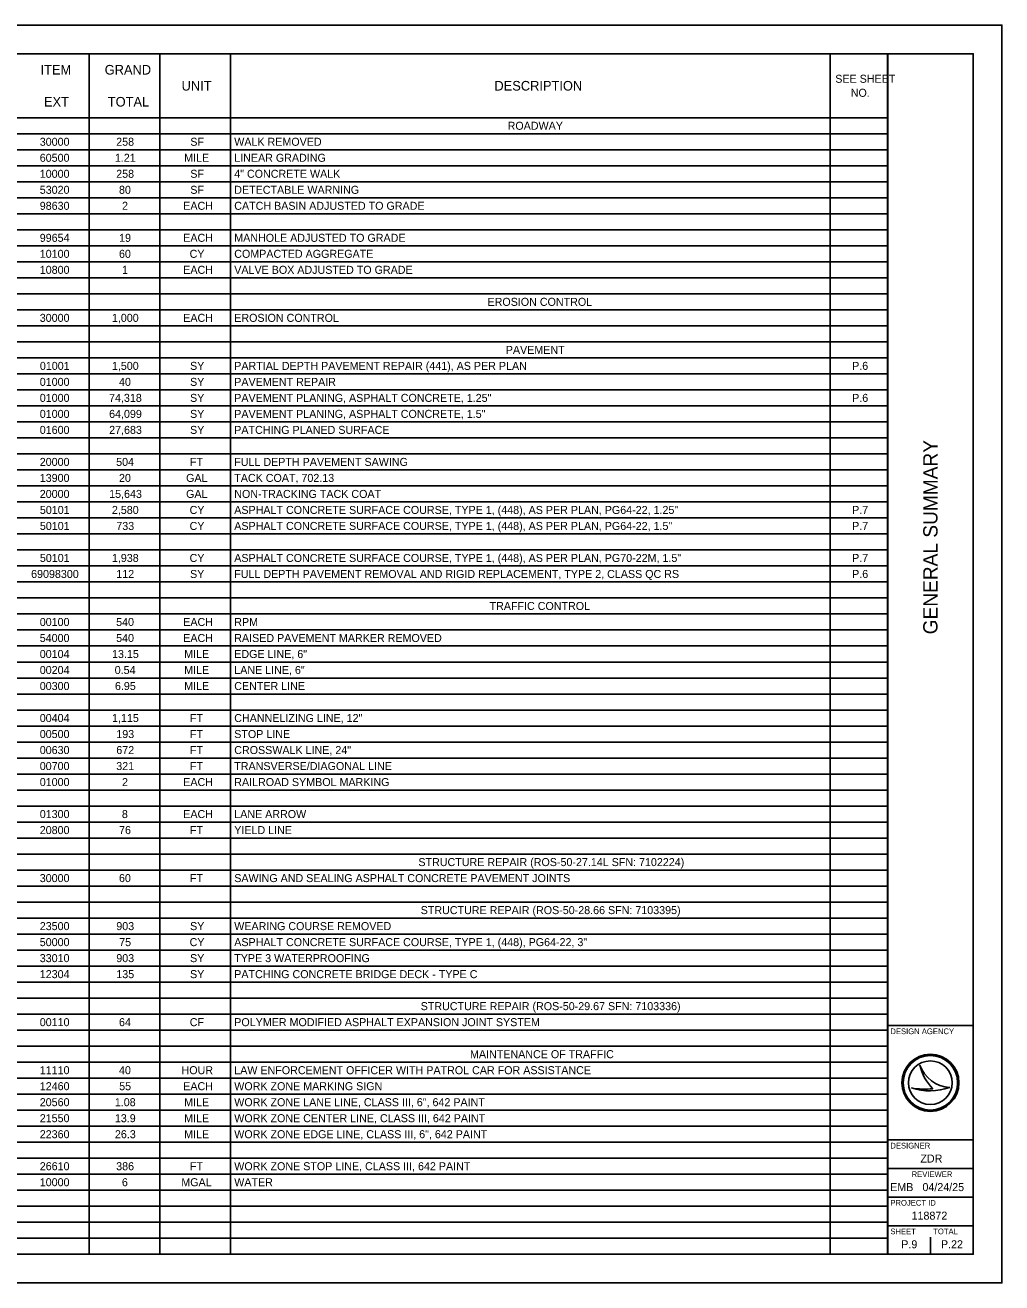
# Model space of a CAD drawing. Extents: x 0 to 34, y 0 to 22.
# Drawn here: x 16.92 to 34, y 0 to 22 of the extents above; entities that cross this region are included whole.
import ezdxf

# ---------------------------------------------------------------- set-up
doc = ezdxf.new("R2010")
doc.units = 0
for name, color, linetype in [('SH_Border', 7, 'Continuous'), ('SH_Cut_Line', 7, 'Continuous'), ('SH_Data', 7, 'Continuous'), ('SH_Text', 7, 'Continuous')]:
    doc.layers.add(name, color=color, linetype=linetype)

msp = doc.modelspace()

# ---------------------------------------------------------------- linework, layer by layer
at = {"layer": 'SH_Border'}
for p, q in [((32, 0.5), (32, 21.5)), ((32, 4.5), (33.5, 4.5)), ((32, 2.5), (33.5, 2.5)), ((32, 2), (33.5, 2)), ((32, 1.5), (33.5, 1.5)), ((32, 1), (33.5, 1))]:
    msp.add_line(p, q, dxfattribs=at)
msp.add_lwpolyline([(1.5, 21.5), (33.5, 21.5), (33.5, 0.5), (1.5, 0.5)], close=True, dxfattribs=at)
at = {"layer": 'SH_Cut_Line'}
msp.add_lwpolyline([(0, 0), (34, 0), (34, 22), (0, 22)], close=True, dxfattribs=at)
at = {"layer": 'SH_Data'}
for p, q in [((32.567, 3.81), (32.567, 3.81)), ((32.417, 3.41), (32.417, 3.41)), ((32.75, 3.5), (32.75, 3.5)), ((33.087, 3.419), (33.087, 3.419)), ((32.375, 0.675), (32.375, 0.675)), ((32.75, 0.5), (32.75, 0.8))]:
    msp.add_line(p, q, dxfattribs=at)
for radius in [0.5, 0.477, 0.477, 0.382]:
    msp.add_circle((32.75, 3.5), radius, dxfattribs=at)
for centre, radius, start, end in [((33.116, 3.998), 0.58, 198.9257, 198.9319), ((33.347, 3.97), 0.796, 191.6379, 191.6421), ((33.116, 3.998), 0.58, 198.9319, 267.1657), ((33.347, 3.97), 0.796, 191.6421, 226.0947), ((32.739, 4.37), 1.013, 251.4576, 290.0832), ((32.648, 4.654), 1.266, 259.4964, 259.4995), ((32.739, 4.37), 1.013, 251.4527, 251.4576), ((32.648, 4.654), 1.266, 259.4995, 276.6672)]:
    msp.add_arc(centre, radius, start, end, dxfattribs=at)
at = {"layer": 'SH_Text'}
for p, q in [((1.5, 21.5), (32.004, 21.5)), ((18.036, 21.5), (18.036, 0.5)), ((19.272, 21.5), (19.272, 0.5)), ((20.507, 21.5), (20.507, 0.5)), ((30.999, 21.5), (30.999, 0.5)), ((32.004, 21.5), (32.004, 0.5)), ((1.5, 20.38), (32.004, 20.38)), ((1.5, 20.1), (32.004, 20.1)), ((1.5, 19.82), (32.004, 19.82)), ((1.5, 19.54), (32.004, 19.54)), ((1.5, 19.26), (32.004, 19.26)), ((1.5, 18.98), (32.004, 18.98)), ((1.5, 18.7), (32.004, 18.7)), ((1.5, 18.42), (32.004, 18.42)), ((1.5, 18.14), (32.004, 18.14)), ((1.5, 17.86), (32.004, 17.86)), ((1.5, 17.58), (32.004, 17.58)), ((1.5, 17.3), (32.004, 17.3)), ((1.5, 17.02), (32.004, 17.02)), ((1.5, 16.74), (32.004, 16.74)), ((1.5, 16.46), (32.004, 16.46)), ((1.5, 16.18), (32.004, 16.18)), ((1.5, 15.9), (32.004, 15.9)), ((1.5, 15.62), (32.004, 15.62)), ((1.5, 15.34), (32.004, 15.34)), ((1.5, 15.06), (32.004, 15.06)), ((1.5, 14.78), (32.004, 14.78)), ((1.5, 14.5), (32.004, 14.5)), ((1.5, 14.22), (32.004, 14.22)), ((1.5, 13.94), (32.004, 13.94)), ((1.5, 13.66), (32.004, 13.66)), ((1.5, 13.38), (32.004, 13.38)), ((1.5, 13.1), (32.004, 13.1)), ((1.5, 12.82), (32.004, 12.82)), ((1.5, 12.54), (32.004, 12.54)), ((1.5, 12.26), (32.004, 12.26)), ((1.5, 11.98), (32.004, 11.98)), ((1.5, 11.7), (32.004, 11.7)), ((1.5, 11.42), (32.004, 11.42)), ((1.5, 11.14), (32.004, 11.14)), ((1.5, 10.86), (32.004, 10.86)), ((1.5, 10.58), (32.004, 10.58)), ((1.5, 10.3), (32.004, 10.3)), ((1.5, 10.02), (32.004, 10.02)), ((1.5, 9.74), (32.004, 9.74)), ((1.5, 9.46), (32.004, 9.46)), ((1.5, 9.18), (32.004, 9.18)), ((1.5, 8.9), (32.004, 8.9)), ((1.5, 8.62), (32.004, 8.62)), ((1.5, 8.34), (32.004, 8.34)), ((1.5, 8.06), (32.004, 8.06)), ((1.5, 7.78), (32.004, 7.78)), ((1.5, 7.5), (32.004, 7.5)), ((1.5, 7.22), (32.004, 7.22)), ((1.5, 6.94), (32.004, 6.94)), ((1.5, 6.66), (32.004, 6.66)), ((1.5, 6.38), (32.004, 6.38)), ((1.5, 6.1), (32.004, 6.1)), ((1.5, 5.82), (32.004, 5.82)), ((1.5, 5.54), (32.004, 5.54)), ((1.5, 5.26), (32.004, 5.26)), ((1.5, 4.98), (32.004, 4.98)), ((1.5, 4.7), (32.004, 4.7)), ((1.5, 4.42), (32.004, 4.42)), ((1.5, 4.14), (32.004, 4.14)), ((1.5, 3.86), (32.004, 3.86)), ((1.5, 3.58), (32.004, 3.58)), ((1.5, 3.3), (32.004, 3.3)), ((1.5, 3.02), (32.004, 3.02)), ((1.5, 2.74), (32.004, 2.74)), ((1.5, 2.46), (32.004, 2.46)), ((1.5, 2.18), (32.004, 2.18)), ((1.5, 1.9), (32.004, 1.9)), ((1.5, 1.62), (32.004, 1.62)), ((1.5, 1.34), (32.004, 1.34)), ((1.5, 1.06), (32.004, 1.06)), ((1.5, 0.78), (32.004, 0.78)), ((1.5, 0.5), (32.004, 0.5))]:
    msp.add_line(p, q, dxfattribs=at)

# ---------------------------------------------------------------- texts
at = {"layer": 'SH_Data'}
msp.add_text('GENERAL SUMMARY', height=0.25, rotation=90, dxfattribs=at).set_placement((32.875, 11.344))
for s, height, p in [('DESIGN AGENCY', 0.1, (32.05, 4.35)), ('DESIGNER', 0.1, (32.05, 2.35)), ('ZDR', 0.14, (32.575, 2.105)), ('REVIEWER', 0.1, (32.422, 1.85)), ('EMB', 0.14, (32.047, 1.605)), ('04/24/25', 0.14, (32.611, 1.605)), ('PROJECT ID', 0.1, (32.05, 1.35)), ('118872', 0.14, (32.421, 1.105)), ('SHEET', 0.1, (32.05, 0.85)), ('TOTAL', 0.1, (32.8, 0.85)), ('P.9', 0.14, (32.24, 0.605)), ('P.22', 0.14, (32.935, 0.605))]:
    msp.add_text(s, height=height, dxfattribs=at).set_placement(p)
at = {"layer": 'SH_Text'}
for s, height, p in [('ITEM', 0.168, (17.184, 21.136)), ('GRAND', 0.168, (18.307, 21.136)), ('SEE SHEET ', 0.14, (31.086, 20.992)), ('UNIT', 0.168, (19.652, 20.856)), ('DESCRIPTION', 0.168, (25.124, 20.856)), ('EXT', 0.168, (17.244, 20.576)), ('TOTAL', 0.168, (18.361, 20.576)), ('NO.', 0.14, (31.357, 20.747)), ('ROADWAY', 0.14, (25.355, 20.17)), ('30000', 0.14, (17.171, 19.89)), ('258', 0.14, (18.508, 19.89)), ('SF', 0.14, (19.804, 19.89)), ('WALK REMOVED', 0.14, (20.573, 19.89)), ('60500', 0.14, (17.171, 19.61)), ('1.21', 0.14, (18.485, 19.61)), ('MILE', 0.14, (19.697, 19.61)), ('LINEAR GRADING', 0.14, (20.573, 19.61)), ('10000', 0.14, (17.171, 19.33)), ('258', 0.14, (18.508, 19.33)), ('SF', 0.14, (19.804, 19.33)), ('4" CONCRETE WALK', 0.14, (20.573, 19.33)), ('53020', 0.14, (17.171, 19.05)), ('80', 0.14, (18.557, 19.05)), ('SF', 0.14, (19.804, 19.05)), ('DETECTABLE WARNING', 0.14, (20.573, 19.05)), ('98630', 0.14, (17.171, 18.77)), ('2', 0.14, (18.61, 18.77)), ('EACH', 0.14, (19.681, 18.77)), ('CATCH BASIN ADJUSTED TO GRADE', 0.14, (20.573, 18.77)), ('99654', 0.14, (17.171, 18.21)), ('19', 0.14, (18.559, 18.21)), ('EACH', 0.14, (19.681, 18.21)), ('MANHOLE ADJUSTED TO GRADE', 0.14, (20.573, 18.21)), ('10100', 0.14, (17.171, 17.93)), ('60', 0.14, (18.557, 17.93)), ('CY', 0.14, (19.792, 17.93)), ('COMPACTED AGGREGATE', 0.14, (20.573, 17.93)), ('10800', 0.14, (17.171, 17.65)), ('1', 0.14, (18.61, 17.65)), ('EACH', 0.14, (19.681, 17.65)), ('VALVE BOX ADJUSTED TO GRADE', 0.14, (20.573, 17.65)), ('EROSION CONTROL', 0.14, (25.003, 17.09)), ('30000', 0.14, (17.171, 16.81)), ('1,000', 0.14, (18.433, 16.81)), ('EACH', 0.14, (19.681, 16.81)), ('EROSION CONTROL', 0.14, (20.573, 16.81)), ('PAVEMENT', 0.14, (25.323, 16.25)), ('01001', 0.14, (17.173, 15.97)), ('1,500', 0.14, (18.433, 15.97)), ('SY', 0.14, (19.8, 15.97)), ('PARTIAL DEPTH PAVEMENT REPAIR (441), AS PER PLAN', 0.14, (20.573, 15.97)), ('P.6', 0.14, (31.381, 15.97)), ('01000', 0.14, (17.171, 15.69)), ('40', 0.14, (18.557, 15.69)), ('SY', 0.14, (19.8, 15.69)), ('PAVEMENT REPAIR', 0.14, (20.573, 15.69)), ('01000', 0.14, (17.171, 15.41)), ('74,318', 0.14, (18.383, 15.41)), ('SY', 0.14, (19.8, 15.41)), ('PAVEMENT PLANING, ASPHALT CONCRETE, 1.25"', 0.14, (20.573, 15.41)), ('P.6', 0.14, (31.381, 15.41)), ('01000', 0.14, (17.171, 15.13)), ('64,099', 0.14, (18.384, 15.13)), ('SY', 0.14, (19.8, 15.13)), ('PAVEMENT PLANING, ASPHALT CONCRETE, 1.5"', 0.14, (20.573, 15.13)), ('01600', 0.14, (17.171, 14.85)), ('27,683', 0.14, (18.385, 14.85)), ('SY', 0.14, (19.8, 14.85)), ('PATCHING PLANED SURFACE', 0.14, (20.573, 14.85)), ('20000', 0.14, (17.171, 14.29)), ('504', 0.14, (18.507, 14.29)), ('FT', 0.14, (19.797, 14.29)), ('FULL DEPTH PAVEMENT SAWING', 0.14, (20.573, 14.29)), ('13900', 0.14, (17.171, 14.01)), ('20', 0.14, (18.557, 14.01)), ('GAL', 0.14, (19.731, 14.01)), ('TACK COAT, 702.13', 0.14, (20.573, 14.01)), ('20000', 0.14, (17.171, 13.73)), ('15,643', 0.14, (18.385, 13.73)), ('GAL', 0.14, (19.731, 13.73)), ('NON-TRACKING TACK COAT', 0.14, (20.573, 13.73)), ('50101', 0.14, (17.173, 13.45)), ('2,580', 0.14, (18.433, 13.45)), ('CY', 0.14, (19.792, 13.45)), ('ASPHALT CONCRETE SURFACE COURSE, TYPE 1, (448), AS PER PLAN, PG64-22, 1.25"', 0.14, (20.573, 13.45)), ('P.7', 0.14, (31.381, 13.45)), ('50101', 0.14, (17.173, 13.17)), ('733', 0.14, (18.51, 13.17)), ('CY', 0.14, (19.792, 13.17)), ('ASPHALT CONCRETE SURFACE COURSE, TYPE 1, (448), AS PER PLAN, PG64-22, 1.5"', 0.14, (20.573, 13.17)), ('P.7', 0.14, (31.381, 13.17)), ('50101', 0.14, (17.173, 12.61)), ('1,938', 0.14, (18.433, 12.61)), ('CY', 0.14, (19.792, 12.61)), ('ASPHALT CONCRETE SURFACE COURSE, TYPE 1, (448), AS PER PLAN, PG70-22M, 1.5"', 0.14, (20.573, 12.61)), ('P.7', 0.14, (31.381, 12.61)), ('69098300', 0.14, (17.02, 12.33)), ('112', 0.14, (18.51, 12.33)), ('SY', 0.14, (19.8, 12.33)), ('FULL DEPTH PAVEMENT REMOVAL AND RIGID REPLACEMENT, TYPE 2, CLASS QC RS', 0.14, (20.573, 12.33)), ('P.6', 0.14, (31.381, 12.33)), ('TRAFFIC CONTROL', 0.14, (25.039, 11.77)), ('00100', 0.14, (17.171, 11.49)), ('540', 0.14, (18.507, 11.49)), ('EACH', 0.14, (19.681, 11.49)), ('RPM', 0.14, (20.573, 11.49)), ('54000', 0.14, (17.171, 11.21)), ('540', 0.14, (18.507, 11.21)), ('EACH', 0.14, (19.681, 11.21)), ('RAISED PAVEMENT MARKER REMOVED', 0.14, (20.573, 11.21)), ('00104', 0.14, (17.171, 10.93)), ('13.15', 0.14, (18.435, 10.93)), ('MILE', 0.14, (19.697, 10.93)), ('EDGE LINE, 6"', 0.14, (20.573, 10.93)), ('00204', 0.14, (17.171, 10.65)), ('0.54', 0.14, (18.482, 10.65)), ('MILE', 0.14, (19.697, 10.65)), ('LANE LINE, 6"', 0.14, (20.573, 10.65)), ('00300', 0.14, (17.171, 10.37)), ('6.95', 0.14, (18.486, 10.37)), ('MILE', 0.14, (19.697, 10.37)), ('CENTER LINE', 0.14, (20.573, 10.37)), ('00404', 0.14, (17.171, 9.81)), ('1,115', 0.14, (18.435, 9.81)), ('FT', 0.14, (19.797, 9.81)), ('CHANNELIZING LINE, 12"', 0.14, (20.573, 9.81)), ('00500', 0.14, (17.171, 9.53)), ('193', 0.14, (18.51, 9.53)), ('FT', 0.14, (19.797, 9.53)), ('STOP LINE', 0.14, (20.573, 9.53)), ('00630', 0.14, (17.171, 9.25)), ('672', 0.14, (18.51, 9.25)), ('FT', 0.14, (19.797, 9.25)), ('CROSSWALK LINE, 24"', 0.14, (20.573, 9.25)), ('00700', 0.14, (17.171, 8.97)), ('321', 0.14, (18.509, 8.97)), ('FT', 0.14, (19.797, 8.97)), ('TRANSVERSE/DIAGONAL LINE', 0.14, (20.573, 8.97)), ('01000', 0.14, (17.171, 8.69)), ('2', 0.14, (18.61, 8.69)), ('EACH', 0.14, (19.681, 8.69)), ('RAILROAD SYMBOL MARKING', 0.14, (20.573, 8.69)), ('01300', 0.14, (17.171, 8.13)), ('8', 0.14, (18.608, 8.13)), ('EACH', 0.14, (19.681, 8.13)), ('LANE ARROW', 0.14, (20.573, 8.13)), ('20800', 0.14, (17.171, 7.85)), ('76', 0.14, (18.558, 7.85)), ('FT', 0.14, (19.797, 7.85)), ('YIELD LINE', 0.14, (20.573, 7.85)), ('STRUCTURE REPAIR (ROS-50-27.14L SFN: 7102224)', 0.14, (23.794, 7.29)), ('30000', 0.14, (17.171, 7.01)), ('60', 0.14, (18.557, 7.01)), ('FT', 0.14, (19.797, 7.01)), ('SAWING AND SEALING ASPHALT CONCRETE PAVEMENT JOINTS', 0.14, (20.573, 7.01)), ('STRUCTURE REPAIR (ROS-50-28.66 SFN: 7103395)', 0.14, (23.834, 6.45)), ('23500', 0.14, (17.171, 6.17)), ('903', 0.14, (18.51, 6.17)), ('SY', 0.14, (19.8, 6.17)), ('WEARING COURSE REMOVED', 0.14, (20.573, 6.17)), ('50000', 0.14, (17.171, 5.89)), ('75', 0.14, (18.56, 5.89)), ('CY', 0.14, (19.792, 5.89)), ('ASPHALT CONCRETE SURFACE COURSE, TYPE 1, (448), PG64-22, 3"', 0.14, (20.573, 5.89)), ('33010', 0.14, (17.171, 5.61)), ('903', 0.14, (18.51, 5.61)), ('SY', 0.14, (19.8, 5.61)), ('TYPE 3 WATERPROOFING', 0.14, (20.573, 5.61)), ('12304', 0.14, (17.171, 5.33)), ('135', 0.14, (18.51, 5.33)), ('SY', 0.14, (19.8, 5.33)), ('PATCHING CONCRETE BRIDGE DECK - TYPE C', 0.14, (20.573, 5.33)), ('STRUCTURE REPAIR (ROS-50-29.67 SFN: 7103336)', 0.14, (23.834, 4.77)), ('00110', 0.14, (17.171, 4.49)), ('64', 0.14, (18.557, 4.49)), ('CF', 0.14, (19.795, 4.49)), ('POLYMER MODIFIED ASPHALT EXPANSION JOINT SYSTEM', 0.14, (20.573, 4.49)), ('MAINTENANCE OF TRAFFIC', 0.14, (24.697, 3.93)), ('11110', 0.14, (17.171, 3.65)), ('40', 0.14, (18.557, 3.65)), ('HOUR', 0.14, (19.651, 3.65)), ('LAW ENFORCEMENT OFFICER WITH PATROL CAR FOR ASSISTANCE', 0.14, (20.573, 3.65)), ('12460', 0.14, (17.171, 3.37)), ('55', 0.14, (18.56, 3.37)), ('EACH', 0.14, (19.681, 3.37)), ('WORK ZONE MARKING SIGN', 0.14, (20.573, 3.37)), ('20560', 0.14, (17.171, 3.09)), ('1.08', 0.14, (18.484, 3.09)), ('MILE', 0.14, (19.697, 3.09)), ('WORK ZONE LANE LINE, CLASS III, 6", 642 PAINT', 0.14, (20.573, 3.09)), ('21550', 0.14, (17.171, 2.81)), ('13.9', 0.14, (18.485, 2.81)), ('MILE', 0.14, (19.697, 2.81)), ('WORK ZONE CENTER LINE, CLASS III, 642 PAINT', 0.14, (20.573, 2.81)), ('22360', 0.14, (17.171, 2.53)), ('26.3', 0.14, (18.486, 2.53)), ('MILE', 0.14, (19.697, 2.53)), ('WORK ZONE EDGE LINE, CLASS III, 6", 642 PAINT', 0.14, (20.573, 2.53)), ('26610', 0.14, (17.171, 1.97)), ('386', 0.14, (18.508, 1.97)), ('FT', 0.14, (19.797, 1.97)), ('WORK ZONE STOP LINE, CLASS III, 642 PAINT', 0.14, (20.573, 1.97)), ('10000', 0.14, (17.171, 1.69)), ('6', 0.14, (18.608, 1.69)), ('MGAL', 0.14, (19.647, 1.69)), ('WATER', 0.14, (20.573, 1.69))]:
    msp.add_text(s, height=height, dxfattribs=at).set_placement(p)

doc.saveas('drawing.dxf')
